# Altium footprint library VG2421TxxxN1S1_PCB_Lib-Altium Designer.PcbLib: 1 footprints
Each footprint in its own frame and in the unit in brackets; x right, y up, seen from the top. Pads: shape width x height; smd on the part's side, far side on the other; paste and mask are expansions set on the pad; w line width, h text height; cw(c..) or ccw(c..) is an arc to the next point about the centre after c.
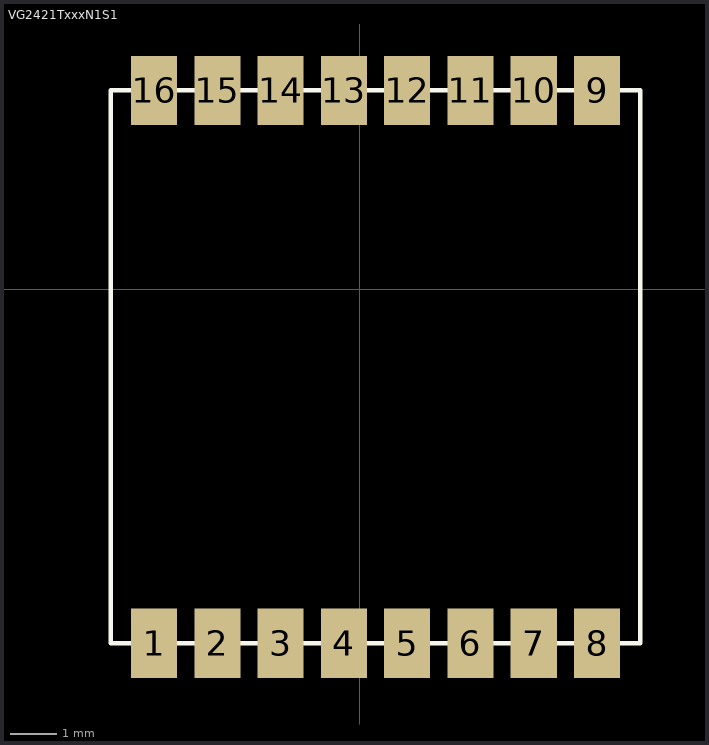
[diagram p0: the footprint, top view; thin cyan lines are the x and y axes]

## VG2421TxxxN1S1 [mm]
pads (17):
  round 1 on Top Overlay: 1(-5.842,-8.255)
  rect 1x1.5 smd: 1(-4.464,-7.692) 2(-3.09,-7.692) 3(-1.715,-7.692) 4(-0.341,-7.692) 5(1.033,-7.692) 6(2.407,-7.692) 7(3.782,-7.692) 8(5.156,-7.692) 9(5.156,4.318) 10(3.782,4.318) 11(2.407,4.318) 12(1.033,4.318) 13(-0.341,4.318) 14(-1.715,4.318) 15(-3.09,4.318) 16(-4.464,4.318)
Top Overlay:
  lines w0.1: -5.404,-7.692 6.096,-7.692 6.096,4.318 -5.404,4.318 -5.404,-7.692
